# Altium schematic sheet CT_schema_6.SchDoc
size 371 x 336 mm
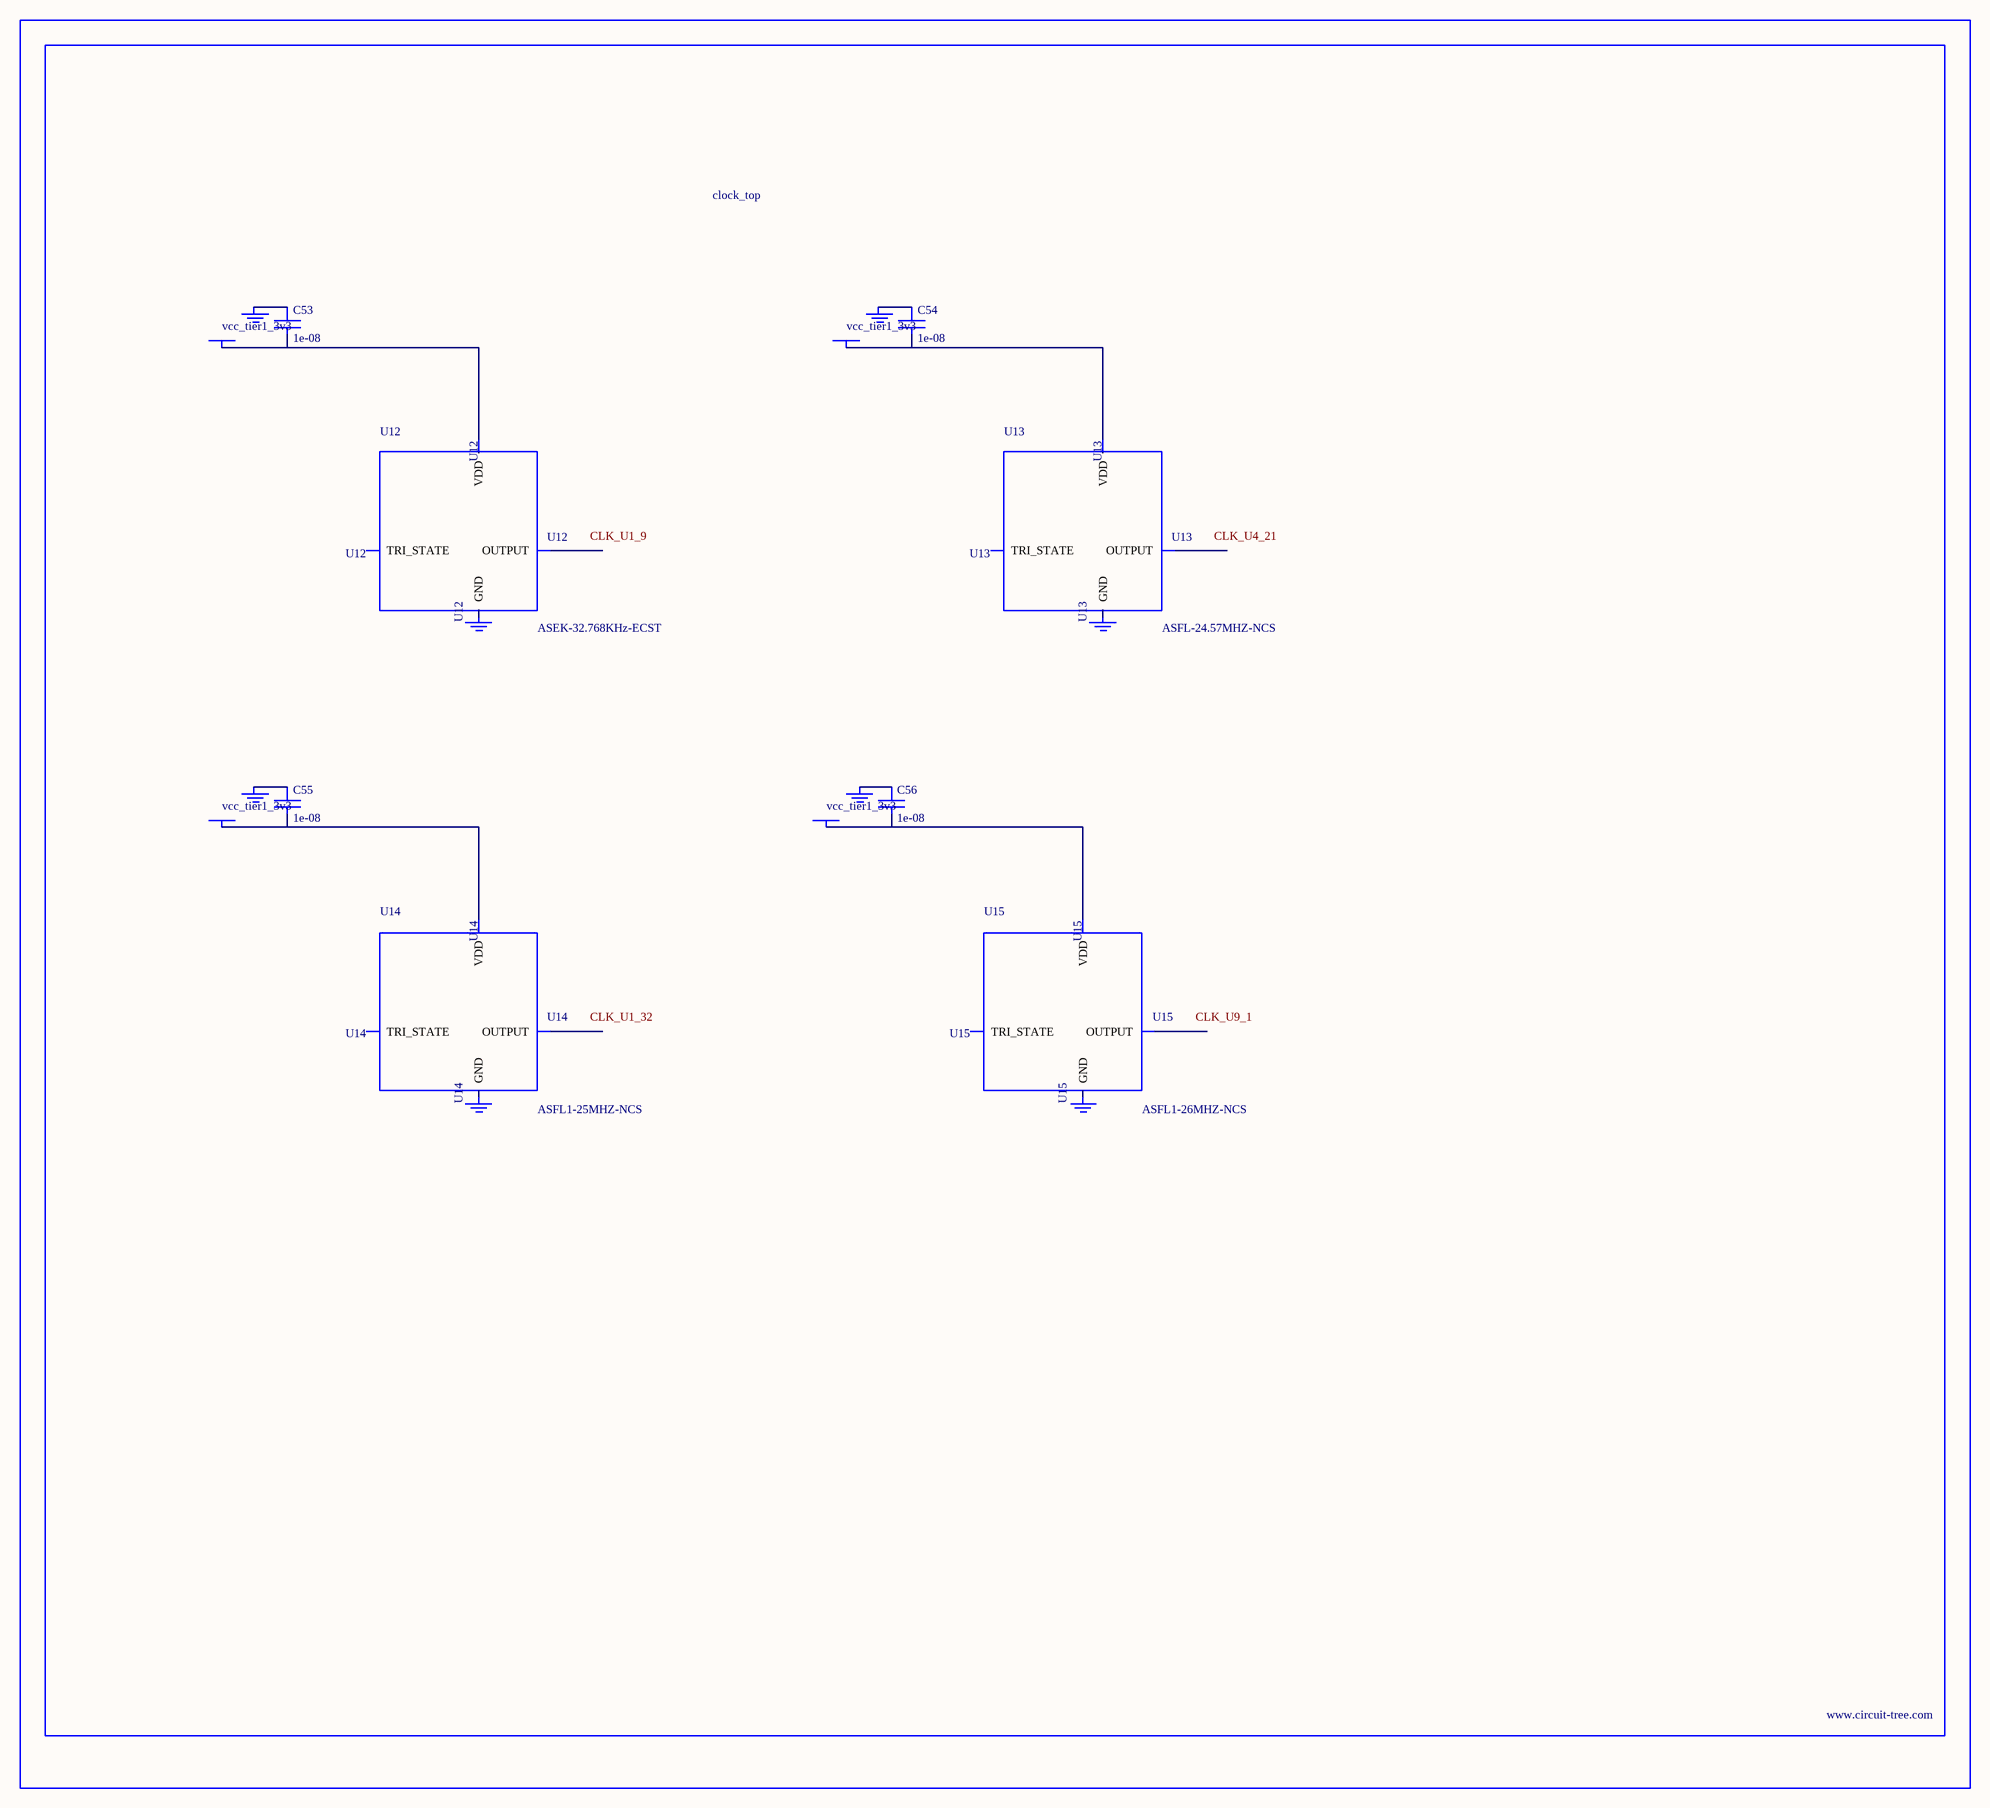
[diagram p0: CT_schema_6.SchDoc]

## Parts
BORDER5  (no value)
C53  1e-08  [C0402]
C54  1e-08  [C0402]
C55  1e-08  [C0402]
C56  1e-08  [C0402]
GND_INSTANCE_5_0  (no value)
GND_INSTANCE_5_1  (no value)
GND_INSTANCE_5_2  (no value)
GND_INSTANCE_5_3  (no value)
GND_INSTANCE_5_4  (no value)
GND_INSTANCE_5_5  (no value)
GND_INSTANCE_5_6  (no value)
GND_INSTANCE_5_7  (no value)
POWER_INSTANCE_5_0  vcc_tier1_3v3
POWER_INSTANCE_5_1  vcc_tier1_3v3
POWER_INSTANCE_5_2  vcc_tier1_3v3
POWER_INSTANCE_5_3  vcc_tier1_3v3
U12  ASEK-32.768KHz-ECST  [ASEK]
U13  ASFL-24.57MHZ-NCS  [ASFL1]
U14  ASFL1-25MHZ-NCS  [ASFL1]
U15  ASFL1-26MHZ-NCS  [ASFL1]

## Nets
NetC53_1: C53.1 GND_INSTANCE_5_0.0(GND)
NetC53_2: C53.2 POWER_INSTANCE_5_0.0(PWR) U12.4(VDD)
NetC54_1: C54.1 GND_INSTANCE_5_2.0(GND)
NetC54_2: C54.2 POWER_INSTANCE_5_1.0(PWR) U13.4(VDD)
NetC55_1: C55.1 GND_INSTANCE_5_4.0(GND)
NetC55_2: C55.2 POWER_INSTANCE_5_2.0(PWR) U14.4(VDD)
NetC56_1: C56.1 GND_INSTANCE_5_6.0(GND)
NetC56_2: C56.2 POWER_INSTANCE_5_3.0(PWR) U15.4(VDD)

Not connected (* = marked no-connect by the designer): GND_INSTANCE_5_1 0(GND); GND_INSTANCE_5_3 0(GND); GND_INSTANCE_5_5 0(GND); GND_INSTANCE_5_7 0(GND); U12 1(TRI_STATE) 2(GND) 3(OUTPUT); U13 1(TRI_STATE) 2(GND) 3(OUTPUT); U14 1(TRI_STATE) 2(GND) 3(OUTPUT); U15 1(TRI_STATE) 2(GND) 3(OUTPUT)

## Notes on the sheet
- Labels drawn without touching a wire or pin: CLK_U1_9, CLK_U1_32, CLK_U4_21, CLK_U9_1

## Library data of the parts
BORDER5 = BORDER_PAGE5
C53-C56 = C0402C103K3RAC
GND_INSTANCE_5_0-GND_INSTANCE_5_7 = GND
POWER_INSTANCE_5_0-POWER_INSTANCE_5_3 = PWR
